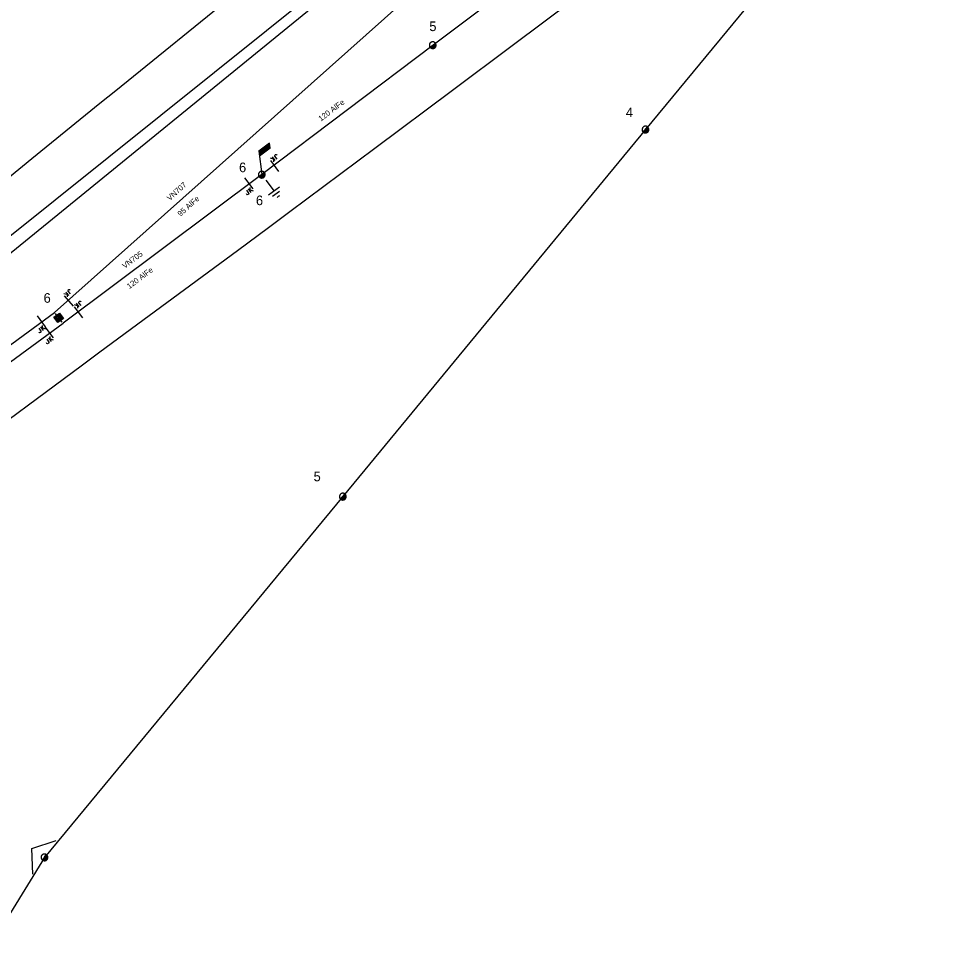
# Model space of a CAD drawing. Extents: x -545588 to -543214, y -1196037 to -1194452.
# Drawn here: x -545402.3 to -545231.8, y -1195194.1 to -1195024.5 of the extents above; entities that cross this region are included whole.
import ezdxf

# ---------------------------------------------------------------- set-up
doc = ezdxf.new("R2010")
doc.units = 0
for name, color, linetype in [('DOPLŇ_POPISY', 7, 'Continuous'), ('ELE_EON', 7, 'Continuous'), ('ELE_EON_POPIS', 7, 'Continuous'), ('Implicitní', 7, 'Continuous'), ('KONEC_VEDENÍ', 7, 'Continuous'), ('POL_ZNAČKA_PRACOVNÍ', 7, 'Continuous'), ('SDEL_EON', 7, 'Continuous'), ('TECH_OCHR_PÁSMO_HRAN', 7, 'Continuous'), ('Vrstva 18', 7, 'Continuous'), ('Vrstva 35', 7, 'Continuous')]:
    doc.layers.add(name, color=color, linetype=linetype)

# ---------------------------------------------------------------- blocks, each defined once
blk = doc.blocks.new('VN840')
at = {"layer": 'POL_ZNAČKA_PRACOVNÍ'}
for points in [[(-0.01, 1.41), (-0.01, -1.09)], [(-1.51, -1.24), (-1.51, -1.15)], [(-1.48, -1.35), (-1.51, -1.24)], [(-1.33, -1.42), (-1.48, -1.35)], [(-1.27, -1.42), (-1.33, -1.42)], [(-1.13, -1.35), (-1.27, -1.42)], [(-1.09, -1.24), (-1.13, -1.35)], [(-1.09, -0.59), (-1.09, -1.24)], [(-0.68, -0.59), (-0.68, -1.42)], [(-0.68, -1.11), (-0.27, -0.59)], [(-0.54, -0.94), (-0.2, -1.42)]]:
    blk.add_lwpolyline(points, dxfattribs=at)
blk = doc.blocks.new('VN860')
at = {"layer": 'POL_ZNAČKA_PRACOVNÍ'}
for points in [[(-3.74, 0), (0.01, 2.82)], [(0.01, 2.82), (3.76, 0)]]:
    blk.add_lwpolyline(points, dxfattribs=at)
blk = doc.blocks.new('VN440')
at = {"layer": 'ELE_EON_POPIS'}
for points in [[(1.22, 0), (1.21, 0.13), (1.19, 0.25), (1.16, 0.38), (1.11, 0.5), (1.05, 0.61), (0.98, 0.72), (0.9, 0.82), (0.81, 0.91), (0.71, 0.99), (0.6, 1.06), (0.49, 1.12), (0.37, 1.16), (0.25, 1.2), (0.12, 1.22), (-0.01, 1.22), (-0.14, 1.22), (-0.26, 1.2), (-0.39, 1.16), (-0.51, 1.12), (-0.62, 1.06), (-0.73, 0.99), (-0.83, 0.91), (-0.92, 0.82), (-1, 0.72), (-1.07, 0.61), (-1.13, 0.5), (-1.18, 0.38), (-1.21, 0.25), (-1.23, 0.13), (-1.24, 0), (-1.23, -0.13), (-1.21, -0.26), (-1.18, -0.38), (-1.13, -0.5), (-1.07, -0.62), (-1, -0.73), (-0.92, -0.83), (-0.83, -0.92), (-0.73, -1), (-0.62, -1.07), (-0.51, -1.13), (-0.39, -1.17), (-0.26, -1.2), (-0.14, -1.23), (-0.01, -1.23), (0.12, -1.23), (0.25, -1.2), (0.37, -1.17), (0.49, -1.13), (0.6, -1.07), (0.71, -1), (0.81, -0.92), (0.9, -0.83), (0.98, -0.73), (1.05, -0.62), (1.11, -0.5), (1.16, -0.38), (1.19, -0.26), (1.21, -0.13), (1.22, 0)], [(-1.24, 0), (1.22, 0)], [(-1.18, -0.34), (1.1, -0.34)], [(-1.01, -0.63), (0.97, -0.63)], [(-0.74, -0.92), (0.68, -0.92)]]:
    blk.add_lwpolyline(points, dxfattribs=at)
blk = doc.blocks.new('VN810')
at = {"layer": 'POL_ZNAČKA_PRACOVNÍ'}
for points in [[(0, -1.25), (0, -3.75)], [(1.25, -3.75), (-1.25, -3.75)], [(0.77, -4.37), (-0.8, -4.37)], [(0, -5), (-0.25, -5)], [(0.27, -5), (0, -5)]]:
    blk.add_lwpolyline(points, dxfattribs=at)
blk = doc.blocks.new('VN001')
at = {"layer": 'Implicitní'}
for p, q in [((1.96, 3.43), (4.37, 3.43)), ((1.99, 3.48), (4.4, 3.48)), ((2.02, 3.53), (4.43, 3.53)), ((2.05, 3.58), (4.46, 3.58)), ((2.07, 3.63), (4.49, 3.63)), ((2.1, 3.68), (4.52, 3.68)), ((2.13, 3.73), (2.54, 3.73)), ((1.73, 3.03), (4.14, 3.03)), ((1.76, 3.08), (4.17, 3.08)), ((1.79, 3.13), (4.2, 3.13)), ((1.82, 3.18), (4.23, 3.18)), ((1.85, 3.23), (4.26, 3.23)), ((1.87, 3.28), (4.29, 3.28)), ((1.9, 3.33), (4.32, 3.33)), ((1.93, 3.38), (4.35, 3.38))]:
    blk.add_line(p, q, dxfattribs=at)
blk.add_lwpolyline([(2.13, 3.73), (0, 0)], dxfattribs=at)
blk.add_lwpolyline([(4.55, 3.73), (2.13, 3.73), (1.7, 2.98), (4.12, 2.99)], close=True, dxfattribs=at)
blk = doc.blocks.new('VN470')
at = {"layer": 'ELE_EON_POPIS'}
for points in [[(-1.23, 1.22), (1.23, 1.22)], [(-1.23, -1.23), (-1.23, 1.22)], [(-0.92, 0.9), (0.92, 0.9)], [(-0.92, -0.95), (-0.92, 0.9)], [(-0.61, 0.61), (0.61, 0.61)], [(-0.61, -0.62), (-0.61, 0.61)], [(-0.31, -0.27), (-0.31, 0.34)], [(-0.31, 0.34), (0.31, 0.34)], [(0, 1.22), (0, 1.97)], [(0.31, 0.34), (0.31, -0.27)], [(0.61, 0.61), (0.61, -0.62)], [(0.92, 0.9), (0.92, -0.95)], [(1.23, 1.22), (1.23, -1.23)], [(1.23, -1.23), (-1.23, -1.23)], [(0.92, -0.95), (-0.92, -0.95)], [(0.61, -0.62), (-0.61, -0.62)], [(0.31, -0.27), (-0.31, -0.27)], [(0, -1.23), (0, -1.98)]]:
    blk.add_lwpolyline(points, dxfattribs=at)

msp = doc.modelspace()

# ---------------------------------------------------------------- linework, layer by layer
at = {"layer": 'ELE_EON'}
for points in [[(-545395.75, -1195077.92), (-545332.4, -1195021.48), (-545278.54, -1194980.38), (-545246.49, -1194956.34)], [(-545240.7, -1194964.34), (-545269.49, -1194986.16), (-545326.84, -1195029.29), (-545358.05, -1195052.83)], [(-545290.02, -1194972.8), (-545405.11, -1195065.07), (-545495.54, -1195139.14), (-545571.44, -1195160.65)], [(-545289.27, -1194973.82), (-545403.67, -1195067.08), (-545494.32, -1195141.28), (-545571.32, -1195163.18)], [(-545231.84, -1194976.41), (-545288.22, -1195044.64), (-545343.3, -1195111.41), (-545397.6, -1195177.04), (-545441.95, -1195249.1), (-545485.78, -1195319.69), (-545525.23, -1195383.69), (-545557.58, -1195435.71)], [(-545358.05, -1195052.83), (-545394.22, -1195079.84)], [(-545570.96, -1195170.23), (-545491.96, -1195148.44), (-545395.75, -1195077.92)], [(-545570.84, -1195172.71), (-545490.55, -1195150.49), (-545394.22, -1195079.84)]]:
    msp.add_lwpolyline(points, dxfattribs=at)
at = {"layer": 'Vrstva 35'}
for points in [[(-545289.91, -1195012.5), (-545312.5, -1195029.39), (-545323.35, -1195037.5), (-545337.5, -1195048.08), (-545352.95, -1195059.63), (-545356.83, -1195062.5), (-545362.5, -1195066.69), (-545378.52, -1195078.52), (-545387.5, -1195085.16), (-545390.67, -1195087.5), (-545412.5, -1195103.63)], [(-545410.48, -1195058.49), (-545399.88, -1195049.88), (-545387.5, -1195039.82), (-545384.64, -1195037.5), (-545362.5, -1195019.51)]]:
    msp.add_lwpolyline(points, dxfattribs=at)

# ---------------------------------------------------------------- block references
at = {"layer": 'DOPLŇ_POPISY'}
for name, p, xscale, yscale, rotation in [('VN440', (-545326.94, -1195029.28), 0.5, 0.5000000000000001, 37.1260583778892), ('VN440', (-545288.22, -1195044.63), 0.49999999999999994, 0.5000000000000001, 50.42141944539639), ('VN440', (-545358.05, -1195052.83), 0.5, 0.5, 36.74807496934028), ('VN470', (-545395.02, -1195078.9), 0.5, 0.5, -143.35134994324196), ('VN440', (-545343.3, -1195111.41), 0.5, 0.5, 50.396755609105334), ('VN440', (-545397.6, -1195177.04), 0.5, 0.5, 58.389286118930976)]:
    msp.add_blockref(name, p, dxfattribs=dict(at, xscale=xscale, yscale=yscale, rotation=rotation))
at = {"layer": 'POL_ZNAČKA_PRACOVNÍ', "rotation": 36.748008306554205}
msp.add_blockref('VN810', (-545358.05, -1195052.83), dxfattribs=at)
at = {"layer": 'TECH_OCHR_PÁSMO_HRAN', "rotation": 36.748177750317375}
msp.add_blockref('VN001', (-545358.05, -1195052.83), dxfattribs=at)
at = {"layer": 'Vrstva 18'}
for name, p, rotation in [('VN840', (-545355.78, -1195051.12), -142.97507770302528), ('VN840', (-545360.32, -1195054.53), 36.74898342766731), ('VN840', (-545393.26, -1195075.7), -138.30348056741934), ('VN840', (-545391.47, -1195077.79), -143.2516889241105), ('VN840', (-545398.11, -1195079.65), 36.24423325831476), ('VN840', (-545396.67, -1195081.64), 36.256725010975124), ('VN860', (-545397.6, -1195177.04), 55.01536398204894)]:
    msp.add_blockref(name, p, dxfattribs=dict(at, rotation=rotation))

# ---------------------------------------------------------------- texts
at = {"layer": 'ELE_EON_POPIS'}
for s, rotation, p in [('120 AlFe', 37.025, (-545347.29, -1195043.19)), ('95 AlFe', 41.697, (-545372.85, -1195060.51)), ('120 AlFe', 36.748, (-545382.15, -1195073.68))]:
    msp.add_text(s, height=1, rotation=rotation, dxfattribs=at).set_placement(p)
at = {"layer": 'KONEC_VEDENÍ'}
msp.add_text('6', height=1.75, dxfattribs=at).set_placement((-545359.12, -1195058.39))
at = {"layer": 'POL_ZNAČKA_PRACOVNÍ'}
for s, p in [('5', (-545327.56, -1195026.72)), ('4', (-545291.79, -1195042.37)), ('6', (-545362.19, -1195052.39)), ('6', (-545397.76, -1195076.14)), ('5', (-545348.62, -1195108.62))]:
    msp.add_text(s, height=1.75, dxfattribs=at).set_placement(p)
at = {"layer": 'SDEL_EON'}
for s, rotation, p in [('VN707', 41.697, (-545374.79, -1195057.65)), ('VN705', 36.748, (-545382.99, -1195069.98))]:
    msp.add_text(s, height=1, rotation=rotation, dxfattribs=at).set_placement(p)

doc.saveas('drawing.dxf')
